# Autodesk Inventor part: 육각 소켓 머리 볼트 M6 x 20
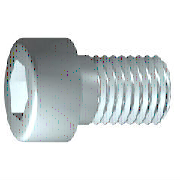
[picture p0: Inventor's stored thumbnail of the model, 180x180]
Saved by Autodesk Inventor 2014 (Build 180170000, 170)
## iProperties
IsCustomPart: 1
Created: 2012-02
Part Number: 육각 소켓 머리 볼트 M6 x 20
Material: 강철, 연강
Description: 6각 소켓 머리 캡 나사
Document SubType Name: Modeling
Standard: ISO 4762
Designer: mdu-01
Standard Revision: Fourth edition 2004-03-01
Standards Organization: ISO
Language: ko-KR
Size Designation: M6 x 20
Categories: <MemberInstance><Categories><Category DisplayName="조임쇠" InternalName="e4da775c-781d-43d5-af7c-5136215cf5a6" Mnemonic="FSTN"><Category DisplayName="볼트" InternalN
Density: 7.86 g/cm^3
Appearance: 강철
Mass: 7.48273 g
Surface Area: 7.641 cm^2
Volume: 0.952002 cm^3
Author: mdu-01
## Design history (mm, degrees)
sketch "스케치1"
  geometry: L1 (-1.333, 0)-(20, 0); L2 (20, 0)-(20, 3); L3 (20, 3)-(2.5, 3); L4 (2.5, 3)-(1.886, 3); L5 (1.886, 3)-(0, 3); L6 (0, 3)-(0, 5); L7 (0, 5)-(-6, 5); L8 (-6, 5)-(-6, 2.887); L9 (-6, 2.887)-(-3, 2.887); L10 (-3, 2.887)-(-1.333, 0); L11 (-11.2, 0)-(25.2, 0) reference; L12 (0, -1)-(0, 6) reference; L13 (2.5, 3)-(0, 3)
  constraints: 22 end point, 6 parallel, 2 collinear, 2 perpendicular, 1 horizontal, 1 point on line
  dimensions: "d1" = 17.5 distance from line of L3.end L2 (= GEL); "d2" = 0.61355 distance of L4.end L3.end (computed from GAL); "d3" = 6 distance between parallel lines of L8 L6 (= KOH); "d4" = 3 distance of L8.end L9.end (= INTI); "d5" = 60 deg angle of L10 L1; "d6" = 6 diameter of L3 L1 (= GD); "d7" = 6 diameter of L5 L1 (= BDM); "d8" = 5.7735 diameter of L9 L1 (= 1.1547 x SW); "d9" = 10 diameter of L7 L1 (= KOD); "d26" = 20 distance between parallel lines of L12 L2 (= NLG)
revolve "본체" sketch "스케치1" stored, may be unused: angle "d10" = 90 deg
sketch "스케치2"
  geometry: L1 (0, -7)-(0, 7) reference; L2 (-7, 0)-(7, 0) reference; L3 (2.887, 0)-(1.443, -2.5); L4 (1.443, -2.5)-(-1.443, -2.5); L5 (-1.443, -2.5)-(-2.887, 0); L6 (-2.887, 0)-(-1.443, 2.5); L7 (-1.443, 2.5)-(1.443, 2.5); L8 (1.443, 2.5)-(2.887, 0); 2 further points
  constraints: 12 end point, 1 coincident, 1 horizontal alignment, 1 point on line, 12 other
extrude "슬롯" join sketch "스케치2" stored distance "d11" = 10; taper "d12" = 0 deg
workplane "Work Plane1"
fillet "Fillet2" dims "d30" = 0.1 (= R)
body "Solid1"
fillet "모깎기1" dims "d17" = 0.6 (= RR)
feature "스레드" dims "d13" = 17.5 (= GEL), "d14" = 0
chamfer "모따기1" distance "d15" = 0.61345 (= -0.5 x SPD + 0.5 x GD); stored, may be unused: second distance "d16" = 0.61345 (= GUL), angle "d27" = 45 deg
other parameters: "GD" = 6 [user parameter; used in 2 equation terms], "NLG" = 20 [user parameter; used in 1 equation term], "GEL" = 17.5 [user parameter; used in 2 equation terms], "KOD" = 10 [user parameter; used in 1 equation term], "KOH" = 6 [user parameter; used in 1 equation term], "INTI" = 3 [user parameter; used in 1 equation term], "GAL" = 0.61345 (= 0.61345 x PTC) [user parameter; used in 1 equation term], "GUL" = 0.61345 (= 0.61345 x PTC) [user parameter; used in 1 equation term], "BDM" = 6 (= NND) [user parameter; used in 1 equation term], "SW" = 5 [user parameter; used in 2 equation terms], "RR" = 0.6 [user parameter; used in 1 equation term], "SPD" = 4.7731 (= NND - 1.2269 x PTC) [user parameter; used in 1 equation term], "d19" = 0, "d28" = 0, "d29" = 0, "R" = 0.1 [user parameter; used in 1 equation term], "TOA" = 30 deg [user parameter], "GD1" = 4.7731 (= THREADDIA - 1.2269 x PTC) [user parameter], "THREADDIA" = 6 [user parameter; used in 1 equation term], "FAWI" = 45 deg [user parameter], "PTC" = 1 [user parameter; used in 5 equation terms], "NND" = 6 [user parameter; used in 2 equation terms], "E0" = 5.775 (= 1.155 x SW) [user parameter]
